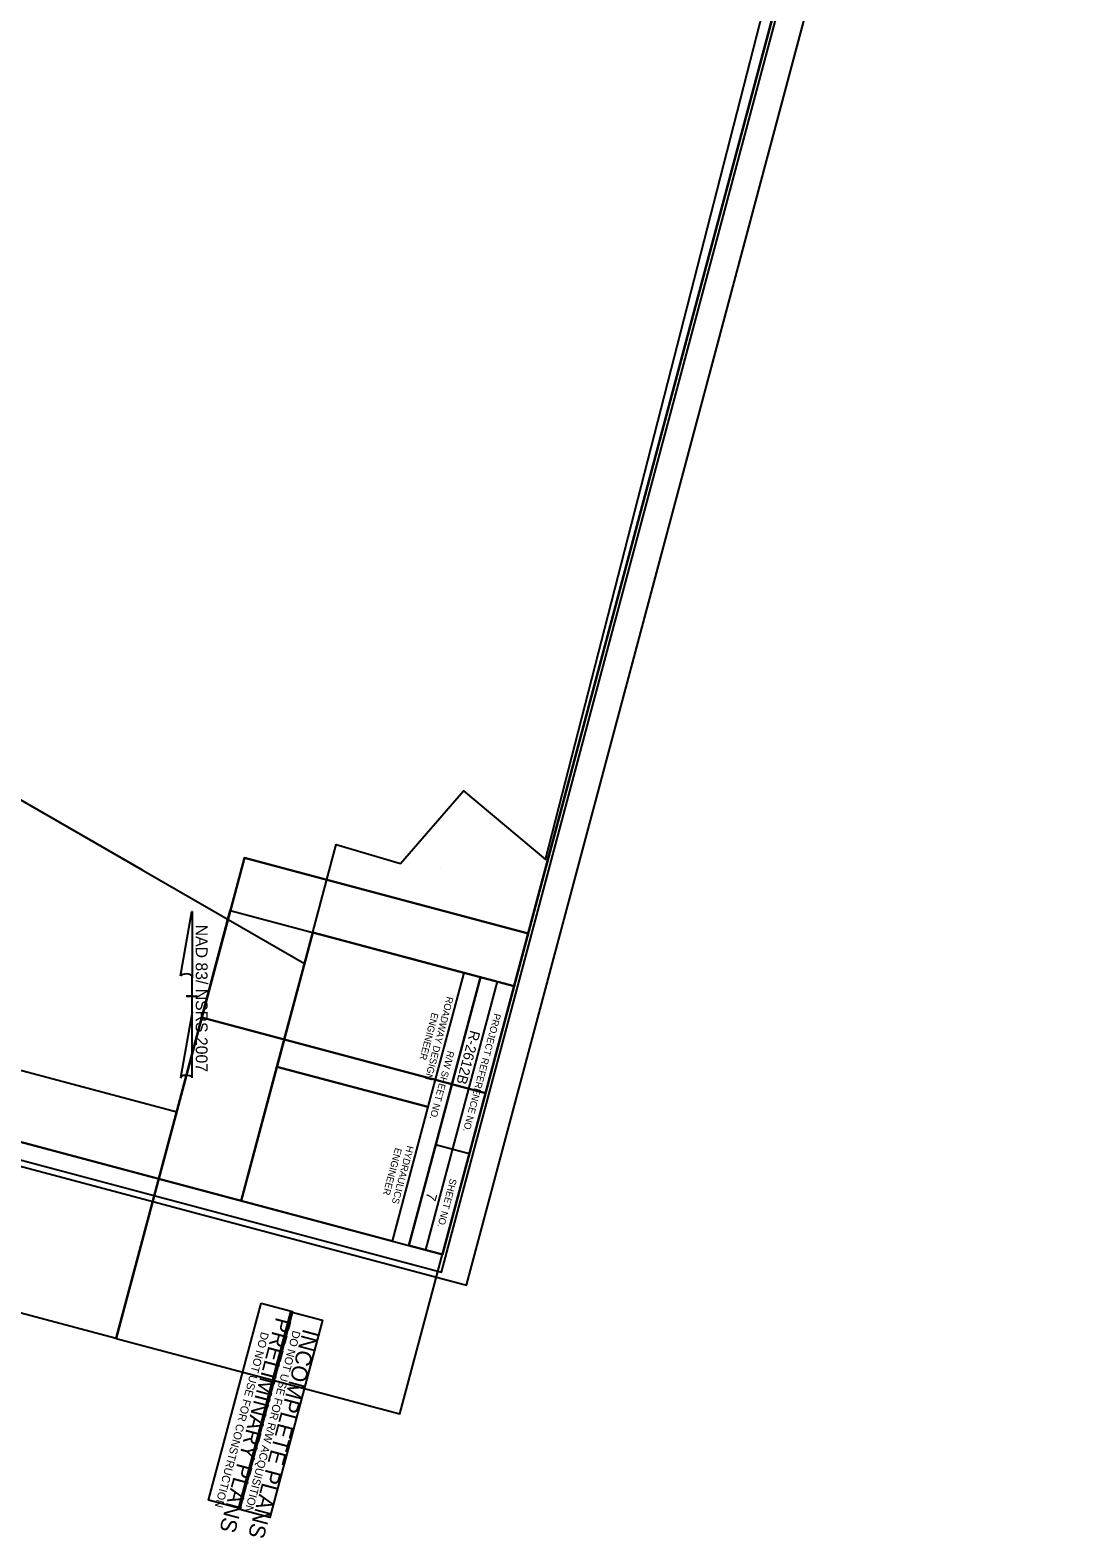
# Model space of a CAD drawing. Extents: x 1782179 to 1783675, y 813964 to 816136.
# Drawn here: x 1782927 to 1783675, y 813964 to 815050 of the extents above; entities that cross this region are included whole.
import ezdxf

# ---------------------------------------------------------------- set-up
doc = ezdxf.new("R2010")
doc.units = 0
for name, color, linetype in [('Matchline', 7, 'Continuous'), ('Prop North Arrow NAD83 for Plan Sheets CELL', 7, 'Continuous'), ('Sheet Clip Boundary CELL', 7, 'Continuous'), ('Sheet Cutting Line CELL', 7, 'Continuous'), ('Sheet Data Field CELL', 7, 'Continuous'), ('Sheet Layout Plan Border', 7, 'Continuous'), ('Sheet North Arrow Point CELL', 7, 'Continuous'), ('Sheet Plan CELL', 7, 'Continuous'), ('Sheet Plan Layout CELL', 7, 'Continuous'), ('Sheet Plot Border Inside CELL', 7, 'Continuous'), ('Sheet Plot Border Outside CELL', 7, 'Continuous'), ('Sheet Sticker Incomplete CELL', 7, 'Continuous'), ('Sheet Sticker Preliminary CELL', 7, 'Continuous')]:
    doc.layers.add(name, color=color, linetype=linetype)

msp = doc.modelspace()

# ---------------------------------------------------------------- linework, layer by layer
at = {"layer": 'Matchline'}
msp.add_line((1783008.6, 814444.4), (1782507.5, 814733.2), dxfattribs=at)
at = {"layer": 'Prop North Arrow NAD83 for Plan Sheets CELL'}
for p, q in [((1783035.5, 814368.4), (1783043.7, 814414.8)), ((1783043.8, 814414.8), (1783043.7, 814414.8)), ((1783043.8, 814414.8), (1783043.7, 814414.8)), ((1783043.8, 814414.8), (1783043.8, 814367)), ((1783043.8, 814342.2), (1783043.8, 814368.4)), ((1783043.8, 814367), (1783043.8, 814368.3)), ((1783039.8, 814353.8), (1783039.7, 814353.8)), ((1783039.8, 814353.8), (1783047.8, 814353.8)), ((1783043.3, 814353.8), (1783039.8, 814353.8)), ((1783043.8, 814342.2), (1783035.4, 814294.9)), ((1783043.8, 814295.1), (1783043.8, 814342.2))]:
    msp.add_line(p, q, dxfattribs=at)
for centre, start_param, end_param in [((1783039.7, 814367.9), 0.216388, 2.908219), ((1783039.7, 814294.8), 0.201328, 3.141593)]:
    msp.add_ellipse(centre, major_axis=(4.23, -0.03), ratio=0.461098, start_param=start_param, end_param=end_param, dxfattribs=at)
at = {"layer": 'Sheet Clip Boundary CELL'}
msp.add_lwpolyline([(1782607.1, 815866.5), (1782558.9, 815688.6), (1782520.3, 815177.9), (1782448.8, 814938.8), (1782554.3, 814867.2), (1782519.6, 814798.9), (1782507.5, 814733.2), (1783124.8, 814377.4), (1783147.7, 814463.1), (1783193.9, 814449.4), (1783239.4, 814501.8), (1783298.4, 814452.3), (1783593.6, 815603.4)], close=True, dxfattribs=at)
at = {"layer": 'Sheet Cutting Line CELL'}
msp.add_line((1783241.6, 814145.5), (1783675.4, 815772.2), dxfattribs=at)
at = {"layer": 'Sheet Layout Plan Border'}
for points in [[(1782596.2, 815887.7), (1782209.7, 814438.3), (1783019.9, 814222.2), (1783071.4, 814415.5), (1783275.8, 814361), (1783610.8, 815617.1)], [(1782583.3, 815839.3), (1782222.6, 814486.6), (1783032.8, 814270.5), (1783081.5, 814453.4), (1783285.9, 814398.9), (1783597.9, 815568.8)]]:
    msp.add_lwpolyline(points, close=True, dxfattribs=at)
at = {"layer": 'Sheet North Arrow Point CELL'}
msp.add_line((1783222.8, 814445.6), (1783222.8, 814445.6), dxfattribs=at)
msp.add_line((1783222.8, 814445.6), (1783222.8, 814445.6), dxfattribs=at)
at = {"layer": 'Sheet Plan CELL'}
for p, q in [((1783251.6, 814367.5), (1783239.5, 814370.7)), ((1783251.6, 814367.5), (1783239.5, 814370.7)), ((1783251.6, 814367.5), (1783200, 814174.2)), ((1783251.6, 814367.5), (1783200, 814174.2)), ((1783251.6, 814367.5), (1783200, 814174.2)), ((1783251.6, 814367.5), (1783200, 814174.2)), ((1783263.7, 814364.3), (1783212.1, 814171)), ((1783263.7, 814364.3), (1783212.1, 814171)), ((1783213.7, 814274), (1783105, 814303)), ((1783213.7, 814274), (1783105, 814303)), ((1783243.5, 814240.2), (1783219.3, 814246.6)), ((1783243.5, 814240.2), (1783219.3, 814246.6))]:
    msp.add_line(p, q, dxfattribs=at)
for points in [[(1783224.2, 814167.7), (1783610.8, 815617.1), (1782596.2, 815887.7), (1782209.7, 814438.3)], [(1782596.2, 815887.7), (1783610.7, 815617.1), (1783275.8, 814361), (1783130.8, 814399.7), (1783079.2, 814206.4), (1782209.7, 814438.3)], [(1783239.5, 814370.7), (1783213.7, 814274), (1783105, 814303), (1783130.8, 814399.7)], [(1783239.5, 814370.7), (1783213.7, 814274), (1783105, 814303), (1783130.8, 814399.7)], [(1783275.8, 814361), (1783224.2, 814167.7), (1783200, 814174.2), (1783251.6, 814367.5)], [(1783275.8, 814361), (1783224.2, 814167.7), (1783200, 814174.2), (1783251.6, 814367.5)], [(1783213.7, 814274), (1783188, 814177.4), (1783079.2, 814206.4), (1783105, 814303)], [(1783213.7, 814274), (1783188, 814177.4), (1783079.2, 814206.4), (1783105, 814303)]]:
    msp.add_lwpolyline(points, close=True, dxfattribs=at)
at = {"layer": 'Sheet Plan Layout CELL'}
for points in [[(1783610.7, 815617.1), (1782596.2, 815887.7), (1782209.7, 814438.3), (1783019.9, 814222.2), (1783081.5, 814453.4), (1783285.9, 814398.9)], [(1783580.1, 815502.2), (1782565.6, 815772.8), (1782179.1, 814323.4), (1782989.2, 814107.4), (1783050.9, 814338.5), (1783255.2, 814284)], [(1783081.5, 814453.4), (1783019.9, 814222.2), (1783224.2, 814167.7), (1783285.9, 814398.9)], [(1783050.9, 814338.5), (1782989.2, 814107.3), (1783193.6, 814052.8), (1783255.2, 814284)]]:
    msp.add_lwpolyline(points, close=True, dxfattribs=at)
at = {"layer": 'Sheet Plot Border Inside CELL'}
msp.add_lwpolyline([(1782633.3, 816036.6), (1782204.1, 814426.9), (1783223.4, 814155), (1783652.7, 815764.7)], close=True, dxfattribs=at)
at = {"layer": 'Sheet Plot Border Outside CELL'}
msp.add_lwpolyline([(1782617.4, 816054.3), (1782183.6, 814427.7), (1783241.6, 814145.5), (1783675.4, 815772.2)], close=True, dxfattribs=at)
at = {"layer": 'Sheet Sticker Incomplete CELL'}
msp.add_lwpolyline([(1783115, 814126.3), (1783137.7, 814120.3), (1783099.9, 813978.2), (1783077.2, 813984.3)], close=True, dxfattribs=at)
at = {"layer": 'Sheet Sticker Preliminary CELL'}
msp.add_lwpolyline([(1783093.5, 814132.7), (1783116.2, 814126.6), (1783078.3, 813984.6), (1783055.6, 813990.6)], close=True, dxfattribs=at)

# ---------------------------------------------------------------- texts
at = {"layer": 'Prop North Arrow NAD83 for Plan Sheets CELL'}
msp.add_text('NAD 83/ NSRS 2007', height=8.5, rotation=270, dxfattribs=at).set_placement((1783046.5, 814405.3))
at = {"layer": 'Sheet Data Field CELL'}
for s, p in [('R-2612B  ', (1783244.3, 814329.7)), ('7', (1783213.3, 814212.9))]:
    msp.add_text(s, height=7.5, rotation=255.0673, dxfattribs=at).set_placement(p)
at = {"layer": 'Sheet Plan CELL'}
for s, p in [('ROADWAY DESIGN', (1783227.4, 814353.9)), ('ROADWAY DESIGN', (1783227.4, 814353.9)), ('ENGINEER', (1783216.6, 814342.3)), ('ENGINEER', (1783216.6, 814342.3)), ('PROJECT REFERENCE NO.', (1783261.6, 814341.8)), ('PROJECT REFERENCE NO.', (1783261.6, 814341.8)), ('R/W SHEET NO.', (1783228, 814314.8)), ('R/W SHEET NO.', (1783228, 814314.8)), ('ENGINEER', (1783190.2, 814244.9)), ('ENGINEER', (1783190.2, 814244.9)), ('HYDRAULICS', (1783198.8, 814246.5)), ('HYDRAULICS', (1783198.8, 814246.5)), ('SHEET NO.', (1783229.8, 814222.8)), ('SHEET NO.', (1783229.8, 814222.8))]:
    msp.add_text(s, height=5, rotation=255.0673, dxfattribs=at).set_placement(p)
at = {"layer": 'Sheet Sticker Incomplete CELL'}
for s, height, p in [('DO NOT USE FOR R/W ACQUISITION', 5.76, (1783116.5, 814113.3)), ('INCOMPLETE PLANS', 11.52, (1783124, 814114.7))]:
    msp.add_text(s, height=height, rotation=255.0673, dxfattribs=at).set_placement(p)
at = {"layer": 'Sheet Sticker Preliminary CELL'}
for s, height, p in [('PRELIMINARY PLANS', 11.52, (1783104.5, 814123)), ('DO NOT USE FOR CONSTRUCTION', 5.76, (1783093.7, 814112.3))]:
    msp.add_text(s, height=height, rotation=255.0673, dxfattribs=at).set_placement(p)

doc.saveas('drawing.dxf')
